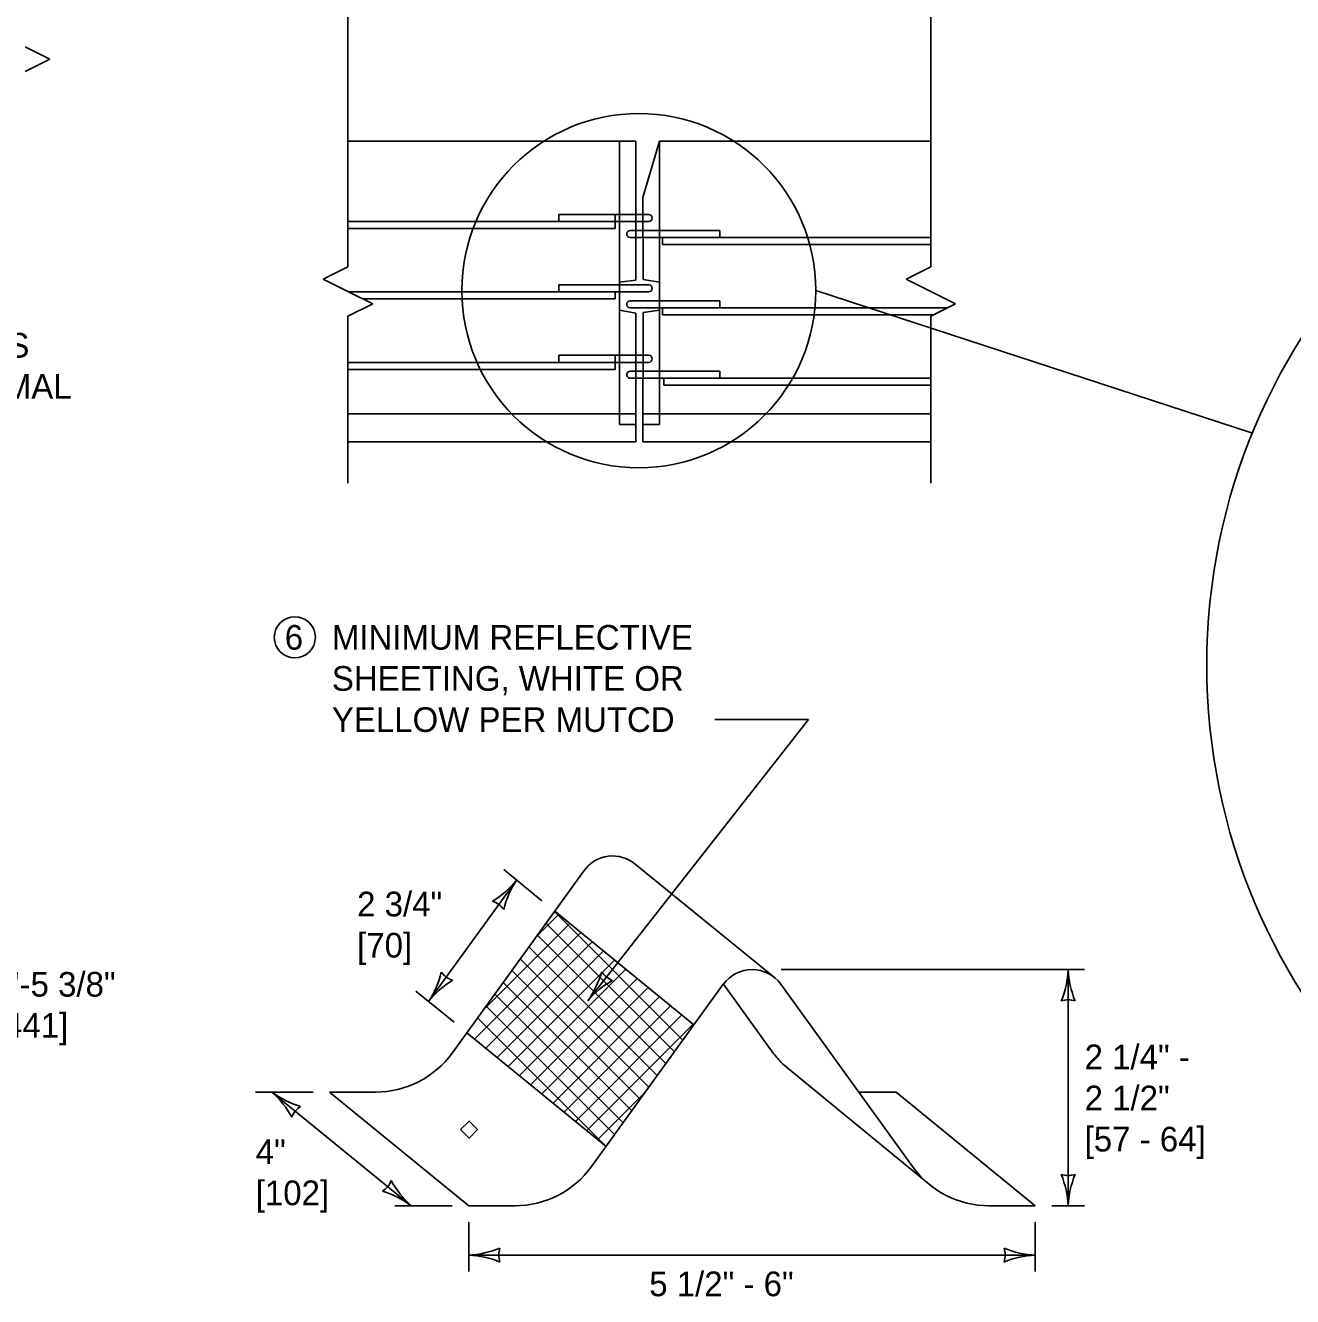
# Model space of a CAD drawing. Extents: x 49991.4 to 50021, y 49987.6 to 50011.4.
# Drawn here: x 50010.586 to 50013.668, y 49992.05 to 49995.141 of the extents above; entities that cross this region are included whole.
import ezdxf

# ---------------------------------------------------------------- set-up
doc = ezdxf.new("R2010")
doc.units = 0
for name, color, linetype in [('Level 1', 7, 'Continuous'), ('Level 2', 7, 'Continuous'), ('Level 3', 7, 'Continuous'), ('Level 4', 7, 'Continuous'), ('Level 6', 7, 'Continuous')]:
    doc.layers.add(name, color=color, linetype=linetype)

msp = doc.modelspace()

# ---------------------------------------------------------------- linework, layer by layer
at = {"layer": 'Level 1'}
for p, q in [((50011.371, 49994.8596), (50012.0713, 49994.8596)), ((50012.0713, 49994.8596), (50012.0713, 49994.5216)), ((50012.0884, 49994.7223), (50012.1284, 49994.8596)), ((50012.1284, 49994.8596), (50012.7886, 49994.8596)), ((50012.0884, 49994.7223), (50012.0885, 49994.5229)), ((50012.0713, 49994.681), (50012.0885, 49994.681)), ((50012.0713, 49994.664), (50012.0885, 49994.664)), ((50012.0713, 49994.6424), (50012.0885, 49994.6424)), ((50012.0713, 49994.625), (50012.0885, 49994.625)), ((50012.0314, 49994.5169), (50012.0713, 49994.5216)), ((50012.1285, 49994.5169), (50012.0885, 49994.5229)), ((50012.0314, 49994.4484), (50012.0314, 49994.5169)), ((50012.0314, 49994.51), (50012.1024, 49994.51)), ((50012.0314, 49994.4929), (50012.1024, 49994.4929)), ((50012.1285, 49994.4484), (50012.1285, 49994.5169)), ((50012.0574, 49994.4712), (50012.1285, 49994.4712)), ((50012.0314, 49994.4484), (50012.0713, 49994.441)), ((50012.0574, 49994.4541), (50012.1285, 49994.4541)), ((50012.0713, 49994.441), (50012.0713, 49994.128)), ((50012.0885, 49994.4424), (50012.0884, 49994.128)), ((50012.1285, 49994.4484), (50012.0885, 49994.4424)), ((50012.0713, 49994.3388), (50012.0885, 49994.3388)), ((50012.0713, 49994.3216), (50012.0885, 49994.3216)), ((50012.0713, 49994.3), (50012.0885, 49994.3)), ((50012.0713, 49994.2829), (50012.0885, 49994.2829)), ((50011.371, 49994.128), (50012.0713, 49994.128)), ((50012.0884, 49994.128), (50012.7886, 49994.128)), ((50012.4083, 49992.8256), (50012.0696, 49993.1018)), ((50011.6243, 49992.6424), (50011.9451, 49993.0858)), ((50011.8292, 49992.9255), (50011.8831, 49992.9795)), ((50011.8732, 49992.9864), (50012.1857, 49992.6739)), ((50011.8737, 49992.9872), (50012.2124, 49992.7109)), ((50011.6997, 49992.7466), (50011.9104, 49992.9573)), ((50011.8524, 49992.9577), (50012.1649, 49992.6452)), ((50011.6789, 49992.6763), (50011.9376, 49992.935)), ((50011.7062, 49992.654), (50011.9649, 49992.9128)), ((50011.8316, 49992.929), (50012.1441, 49992.6165)), ((50011.7334, 49992.6318), (50011.9922, 49992.8905)), ((50011.8109, 49992.9002), (50012.1233, 49992.5878)), ((50011.7607, 49992.6096), (50012.0194, 49992.8683)), ((50011.7901, 49992.8715), (50012.1026, 49992.559)), ((50011.7693, 49992.8428), (50012.0818, 49992.5303)), ((50011.7879, 49992.5873), (50012.0467, 49992.8461)), ((50011.8152, 49992.5651), (50012.074, 49992.8238)), ((50011.7485, 49992.8141), (50012.061, 49992.5016)), ((50011.8425, 49992.5429), (50012.1012, 49992.8016)), ((50011.963, 49992.3661), (50012.2838, 49992.8096)), ((50012.4054, 49992.6424), (50012.2841, 49992.81)), ((50012.7441, 49992.3661), (50012.4233, 49992.8096)), ((50011.707, 49992.7566), (50012.0195, 49992.4442)), ((50011.7278, 49992.7853), (50012.0402, 49992.4729)), ((50011.8697, 49992.5206), (50012.1285, 49992.7794)), ((50011.897, 49992.4984), (50012.1557, 49992.7571)), ((50011.6862, 49992.7279), (50011.9987, 49992.4154)), ((50011.9243, 49992.4762), (50012.183, 49992.7349)), ((50011.9515, 49992.4539), (50012.2103, 49992.7127)), ((50011.66, 49992.6917), (50011.9987, 49992.4154)), ((50012.4279, 49992.6158), (50012.7942, 49992.3156)), ((50011.3259, 49992.5473), (50011.4382, 49992.5473)), ((50011.3259, 49992.5473), (50011.6646, 49992.2711)), ((50011.9788, 49992.4317), (50012.0932, 49992.5461)), ((50012.7039, 49992.5473), (50012.613, 49992.5473)), ((50012.7039, 49992.5473), (50013.0425, 49992.2711)), ((50011.6646, 49992.2711), (50011.7769, 49992.2711)), ((50013.0425, 49992.2711), (50012.9302, 49992.2711))]:
    msp.add_line(p, q, dxfattribs=at)
msp.add_lwpolyline([(50011.6449, 49992.4562), (50011.6655, 49992.4355), (50011.6862, 49992.4562), (50011.6655, 49992.4769)], close=True, dxfattribs=at)
for centre, radius, start, end in [((50012.1024, 49994.5014), 0.00855, 270, 90), ((50012.0574, 49994.4627), 0.00855, 90, 270), ((50012.0149, 49993.0353), 0.0861, 50.5461, 144.119), ((50012.3536, 49992.7591), 0.0861, 35.881, 144.119), ((50011.4382, 49992.777), 0.2297, 270, 324.119), ((50012.5915, 49992.777), 0.2297, 215.881, 224.5527), ((50011.7769, 49992.5007), 0.2297, 270, 324.119), ((50012.9302, 49992.5007), 0.2297, 215.881, 270)]:
    msp.add_arc(centre, radius, start, end, dxfattribs=at)
at = {"layer": 'Level 2'}
msp.add_circle((50011.2417, 49993.653), 0.05, dxfattribs=at)
at = {"layer": 'Level 3'}
for p, q in [((50012.5087, 49994.4959), (50013.5705, 49994.1495)), ((50012.4913, 49993.453), (50011.9541, 49992.7696)), ((50012.2634, 49993.453), (50012.4913, 49993.453)), ((50011.8427, 49993.0124), (50011.7497, 49993.0883)), ((50011.7807, 49993.063), (50011.567, 49992.7675)), ((50013.1625, 49992.8452), (50012.4242, 49992.8452)), ((50013.1225, 49992.2711), (50013.1225, 49992.8452)), ((50011.629, 49992.717), (50011.536, 49992.7928)), ((50011.2859, 49992.5473), (50011.1459, 49992.5473)), ((50011.1859, 49992.5473), (50011.5246, 49992.2711)), ((50011.6246, 49992.2711), (50011.4846, 49992.2711)), ((50013.1625, 49992.2711), (50013.0825, 49992.2711)), ((50011.6646, 49992.2311), (50011.6646, 49992.1111)), ((50013.0425, 49992.2311), (50013.0425, 49992.1111)), ((50011.6646, 49992.1511), (50013.0425, 49992.1511))]:
    msp.add_line(p, q, dxfattribs=at)
for centre, radius in [((50014.9472, 49993.5858), 1.4876), ((50012.0783, 49994.4959), 0.4305)]:
    msp.add_circle(centre, radius, dxfattribs=at)
for centre, radius, start, end in [((50011.6061, 49993.2006), 0.2223, 301.575, 321.7585), ((50011.976, 49992.9359), 0.233, 146.9463, 166.1961), ((50011.7056, 49992.9591), 0.0548, 36.2578, 71.9801), ((50011.3717, 49992.8946), 0.233, 326.9463, 346.1961), ((50011.7416, 49992.6299), 0.2223, 121.575, 141.7585), ((50011.6422, 49992.8714), 0.0548, 216.2578, 251.9801), ((50011.7641, 49992.9043), 0.233, 324.6585, 343.9084), ((50012.1231, 49992.6251), 0.2223, 119.2872, 139.4707), ((50012.0334, 49992.8704), 0.0548, 213.97, 249.6924), ((50012.9004, 49992.8544), 0.2223, 337.456, 357.6395), ((50013.3552, 49992.8567), 0.233, 182.8273, 202.0772), ((50013.1225, 49992.717), 0.0548, 72.1388, 107.8612), ((50011.0384, 49992.381), 0.2223, 28.253, 48.4365), ((50011.3241, 49992.7349), 0.233, 233.6243, 252.8741), ((50011.2853, 49992.4663), 0.0548, 122.9358, 158.6581), ((50011.4252, 49992.3521), 0.0548, 302.9358, 338.6581), ((50011.6721, 49992.4374), 0.2223, 208.253, 228.4365), ((50013.1225, 49992.3993), 0.0548, 252.1388, 287.8612), ((50012.8898, 49992.2596), 0.233, 2.8273, 22.0772), ((50013.3447, 49992.2619), 0.2223, 157.456, 177.6395), ((50011.3864, 49992.0835), 0.233, 53.6243, 72.8741), ((50011.6531, 49992.3838), 0.233, 272.8273, 292.0772), ((50011.6554, 49991.9289), 0.2223, 67.456, 87.6395), ((50011.7928, 49992.1511), 0.0548, 162.1388, 197.8612), ((50013.0517, 49992.3732), 0.2223, 247.456, 267.6395), ((50012.9143, 49992.1511), 0.0548, 342.1388, 17.8612), ((50013.054, 49991.9183), 0.233, 92.8273, 112.0772)]:
    msp.add_arc(centre, radius, start, end, dxfattribs=at)
at = {"layer": 'Level 4'}
for p, q in [((50012.0314, 49994.8596), (50012.0314, 49994.1708)), ((50012.1285, 49994.8596), (50012.1285, 49994.5169)), ((50011.8841, 49994.681), (50011.8841, 49994.664)), ((50011.8841, 49994.681), (50012.0713, 49994.681)), ((50012.0209, 49994.681), (50012.0209, 49994.6467)), ((50012.0885, 49994.681), (50012.1024, 49994.681)), ((50012.0713, 49994.664), (50011.371, 49994.664)), ((50011.371, 49994.6467), (50012.0209, 49994.6467)), ((50012.0713, 49994.6424), (50012.0574, 49994.6424)), ((50012.1024, 49994.664), (50012.0885, 49994.664)), ((50012.2756, 49994.6424), (50012.0885, 49994.6424)), ((50012.2756, 49994.625), (50012.2756, 49994.6424)), ((50012.0574, 49994.625), (50012.0713, 49994.625)), ((50012.0885, 49994.625), (50012.7886, 49994.625)), ((50012.1355, 49994.625), (50012.1355, 49994.608)), ((50012.1355, 49994.608), (50012.7886, 49994.608)), ((50012.0314, 49994.4929), (50011.3729, 49994.4929)), ((50011.8841, 49994.51), (50011.8841, 49994.4929)), ((50011.8841, 49994.51), (50012.0314, 49994.51)), ((50012.0209, 49994.4929), (50012.0209, 49994.4758)), ((50011.4071, 49994.4758), (50012.0209, 49994.4758)), ((50012.2756, 49994.4712), (50012.1285, 49994.4712)), ((50012.2756, 49994.4541), (50012.2756, 49994.4712)), ((50012.1285, 49994.4541), (50012.8293, 49994.4541)), ((50012.1285, 49994.4484), (50012.1285, 49994.1708)), ((50012.1355, 49994.4541), (50012.1355, 49994.4372)), ((50012.1355, 49994.4372), (50012.7953, 49994.4372)), ((50011.8841, 49994.3388), (50011.8841, 49994.3216)), ((50011.8841, 49994.3388), (50012.0713, 49994.3388)), ((50012.0209, 49994.3388), (50012.0209, 49994.3045)), ((50012.0885, 49994.3388), (50012.1024, 49994.3388)), ((50012.0713, 49994.3216), (50011.371, 49994.3216)), ((50011.371, 49994.3045), (50012.0209, 49994.3045)), ((50012.1024, 49994.3216), (50012.0885, 49994.3216)), ((50012.0713, 49994.3), (50012.0574, 49994.3)), ((50012.0574, 49994.2829), (50012.0713, 49994.2829)), ((50012.2756, 49994.3), (50012.0885, 49994.3)), ((50012.0885, 49994.2829), (50012.7886, 49994.2829)), ((50012.1388, 49994.2829), (50012.1388, 49994.2658)), ((50012.2756, 49994.2829), (50012.2756, 49994.3)), ((50012.1388, 49994.2658), (50012.7886, 49994.2658)), ((50012.0713, 49994.1964), (50011.371, 49994.1964)), ((50012.7886, 49994.1964), (50012.0884, 49994.1964)), ((50012.0314, 49994.1708), (50012.0713, 49994.1708)), ((50012.1285, 49994.1708), (50012.0884, 49994.1708))]:
    msp.add_line(p, q, dxfattribs=at)
for centre, radius, start, end in [((50012.1024, 49994.6725), 0.0085, 270, 90), ((50012.0574, 49994.6337), 0.00866, 90.0089, 270.0089), ((50012.1024, 49994.3302), 0.0086, 270, 90), ((50012.0574, 49994.2914), 0.00855, 89.7757, 270.2243)]:
    msp.add_arc(centre, radius, start, end, dxfattribs=at)
at = {"layer": 'Level 6'}
for p, q in [((50011.371, 49994.5538), (50011.371, 49995.464)), ((50012.7886, 49994.5538), (50012.7886, 49995.464)), ((50010.5855, 49995.0884), (50010.6455, 49995.0584)), ((50010.6455, 49995.0584), (50010.5855, 49995.0284)), ((50011.371, 49994.5538), (50011.311, 49994.5238)), ((50012.7886, 49994.5538), (50012.7286, 49994.5238)), ((50011.311, 49994.5238), (50011.371, 49994.4938)), ((50012.7286, 49994.5238), (50012.7886, 49994.4938)), ((50011.371, 49994.4938), (50011.431, 49994.4638)), ((50012.7886, 49994.4938), (50012.8486, 49994.4638)), ((50011.431, 49994.4638), (50011.371, 49994.4338)), ((50012.8486, 49994.4638), (50012.7886, 49994.4338)), ((50011.371, 49994.028), (50011.371, 49994.4338)), ((50012.7886, 49994.028), (50012.7886, 49994.4338))]:
    msp.add_line(p, q, dxfattribs=at)

# ---------------------------------------------------------------- texts
at = {"layer": 'Level 2'}
for s, p in [('HOLE FOR SPECIFIC SITES ', (50009.5396, 49994.3331)), ('SENSITIVE TO SMALL ANIMAL ', (50009.5396, 49994.2331)), ('6', (50011.2172, 49993.623)), ('MINIMUM REFLECTIVE ', (50011.3317, 49993.623)), ('SHEETING, WHITE OR ', (50011.3317, 49993.523)), ('YELLOW PER MUTCD', (50011.3317, 49993.423)), ('2 3/4"', (50011.3932, 49992.9745)), ('[70]', (50011.3932, 49992.8745)), ('1\'-5 3/8"', (50010.5123, 49992.7795)), ('[441]', (50010.5123, 49992.6795)), ('2 1/4" - ', (50013.1625, 49992.603)), ('2 1/2"', (50013.1625, 49992.503)), ('[57 - 64]', (50013.1625, 49992.403)), ('4"', (50011.1466, 49992.3724)), ('[102]', (50011.1466, 49992.2724)), ('5 1/2" - 6"', (50012.1036, 49992.0511))]:
    msp.add_text(s, height=0.06, dxfattribs=at).set_placement(p)

doc.saveas('drawing.dxf')
